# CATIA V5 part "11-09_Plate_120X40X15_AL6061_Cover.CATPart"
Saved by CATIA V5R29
Part number: 11-09_Plate_120X40X15_AL6061_Cover
Source: Unknown
Bounding box of the stored display mesh (mm): x -60 to 60, y -20 to 20, z 0 to 15
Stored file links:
  C:\가치같이\SmartFactory_BoxErectorConveyor\Boxing(under)\11-09_Plate_120X40X15_AL6061_Cover.CATPart
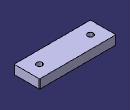
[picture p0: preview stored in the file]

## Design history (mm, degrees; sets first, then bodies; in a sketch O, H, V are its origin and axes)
Body1 (main body)
  Solid1 "PartBody": solid without history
